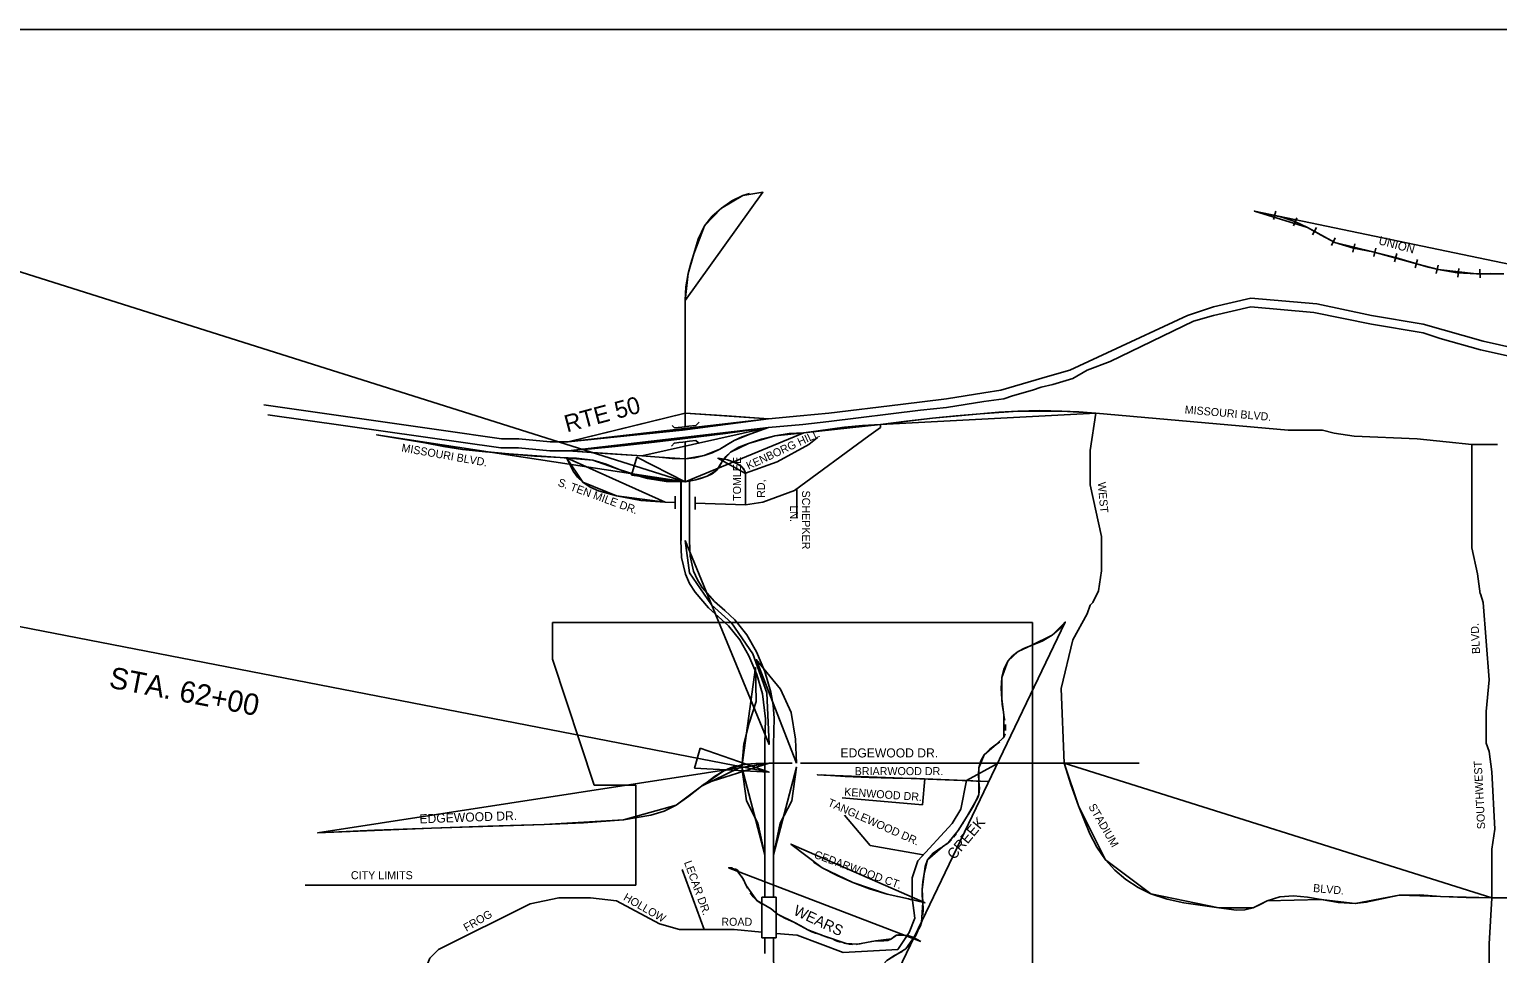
# Model space of a CAD drawing. Extents: x 5.01 to 9.58, y 0.27 to 3.39.
# Drawn here: x 6.043 to 8.037, y 1.964 to 3.219 of the extents above; entities that cross this region are included whole.
import ezdxf

# ---------------------------------------------------------------- set-up
doc = ezdxf.new("R2010")
doc.units = 0
for name, color, linetype in [('Level 7', 7, 'Continuous'), ('MO_001_NOSHOW', 7, 'Continuous'), ('MO_001_VIEW_99', 7, 'Continuous'), ('MO_001_VIEW_PV', 7, 'Continuous')]:
    doc.layers.add(name, color=color, linetype=linetype)

msp = doc.modelspace()

# ---------------------------------------------------------------- linework, layer by layer
at = {"layer": 'Level 7'}
for p, q in [((5.3044, 3.119), (6.9335, 2.6046)), ((6.8604, 2.6137), (6.8679, 2.6381)), ((6.9333, 2.6046), (6.8679, 2.6381)), ((6.8604, 2.6137), (6.9333, 2.6046)), ((5.9971, 2.4143), (7.0472, 2.2101))]:
    msp.add_line(p, q, dxfattribs=at)
msp.add_lwpolyline([(6.9535, 2.2429), (6.9462, 2.2156), (7.0472, 2.2101)], close=True, dxfattribs=at)
at = {"layer": 'MO_001_NOSHOW'}
for points in [[(6.9334, 2.8512), (6.9373, 2.8879), (6.945, 2.9143), (6.9595, 2.9527), (6.9826, 2.9766), (7.0116, 2.9937), (7.0389, 2.998)], [(6.7745, 2.6592), (6.9334, 2.6981)], [(6.9334, 2.6981), (7.0465, 2.6904)], [(7.1984, 2.6828), (7.2692, 2.691), (7.3338, 2.6971), (7.3851, 2.7008), (7.4448, 2.7008), (7.4909, 2.6981)], [(6.7745, 2.6592), (6.9295, 2.6748), (7.0465, 2.6904)], [(6.7745, 2.6592), (6.9334, 2.6759), (7.0465, 2.6904)], [(6.7745, 2.6468), (6.8381, 2.6528), (6.9295, 2.6631), (7.0465, 2.6787)], [(6.8745, 2.6399), (6.8982, 2.6383), (6.9334, 2.6358), (6.9589, 2.6406), (6.9802, 2.6492), (6.9997, 2.661), (7.0223, 2.67), (7.0465, 2.6787)], [(7.0944, 2.6714), (7.1497, 2.6788), (7.1984, 2.6828)], [(6.9334, 2.6046), (6.8823, 2.6092), (6.8439, 2.6216), (6.808, 2.634), (6.7634, 2.6377), (6.694, 2.6426), (6.6308, 2.6488), (6.58, 2.6575), (6.5143, 2.6687)], [(6.9334, 2.6046), (6.948, 2.6075), (6.963, 2.6122), (6.9761, 2.6206), (6.9835, 2.6323), (6.9948, 2.6449), (7.0191, 2.657), (7.0551, 2.6673), (7.0944, 2.6714)], [(6.772, 2.6374), (6.7943, 2.6042), (6.8402, 2.5856), (6.9062, 2.5773)], [(6.7745, 2.6468), (6.8745, 2.6399)], [(7.0154, 2.6159), (7.0141, 2.6203), (7.0096, 2.6257), (7.0032, 2.6294), (6.9991, 2.6315), (6.9949, 2.6332), (6.991, 2.6344), (6.9869, 2.6356), (6.9778, 2.6367)], [(6.9334, 2.5249), (6.9392, 2.4813), (6.9692, 2.4377), (6.9964, 2.4133), (7.025, 2.3711), (7.044, 2.318), (7.0473, 2.2481)], [(7.0844, 2.2226), (7.0833, 2.255), (7.0772, 2.2915), (7.0626, 2.3231), (7.0298, 2.3632)], [(7.0103, 2.217), (7.0128, 2.249), (7.0201, 2.2769), (7.0298, 2.3061), (7.0286, 2.3523)], [(7.0473, 2.2226), (7.0058, 2.2158), (6.9553, 2.1913), (6.9211, 2.1653), (6.8494, 2.1457), (6.7419, 2.1392), (6.5888, 2.1343), (6.4341, 2.1278)], [(6.9613, 2.1955), (6.9859, 2.212), (7.01, 2.2204), (7.0292, 2.2219), (7.0473, 2.2226)], [(7.0415, 2.0982), (7.0322, 2.1408), (7.0164, 2.1712), (7.0103, 2.217)], [(7.0532, 2.0982), (7.0624, 2.1408), (7.0782, 2.1712), (7.0844, 2.217)], [(7.448, 2.2226), (7.4673, 2.1647), (7.5039, 2.0914), (7.5656, 2.0452), (7.6582, 2.0259), (7.7045, 2.0259), (7.7237, 2.0355), (7.797, 2.0374), (7.8433, 2.0317), (7.9031, 2.0432), (7.959, 2.0413), (8.0288, 2.0394)], [(7.3444, 2.1976), (7.3138, 2.1989), (7.2473, 2.2016), (7.1834, 2.2029), (7.1129, 2.2069)], [(7.2592, 2.0326), (7.2366, 2.038), (7.2074, 2.0446), (7.1608, 2.0606), (7.1195, 2.0805), (7.077, 2.1125)], [(7.2533, 1.9801), (7.2426, 1.9863), (7.2311, 1.989), (7.2204, 1.989), (7.2133, 1.9837), (7.192, 1.981), (7.1672, 1.9766), (7.1521, 1.9774), (7.121, 1.9881), (7.0997, 1.9961), (7.0811, 2.0067), (7.0589, 2.0174), (7.05, 2.0245), (7.0305, 2.036), (7.0163, 2.0564), (7.0119, 2.0653), (7.0021, 2.0786), (6.9923, 2.0804)]]:
    msp.add_lwpolyline(points, close=True, dxfattribs=at)
for points in [[(8.0448, 2.8875), (8.0078, 2.8875), (7.956, 2.893), (7.9283, 2.9004), (7.8673, 2.9171), (7.8155, 2.93), (7.7785, 2.9503), (7.7064, 2.9725), (8.9144, 2.7205)], [(7.1814, 1.855), (7.4494, 2.4141), (7.4317, 2.3964), (7.4033, 2.3822), (7.3855, 2.3742), (7.3713, 2.3609), (7.3633, 2.3387), (7.3633, 2.3094), (7.366, 2.2881), (7.366, 2.2579), (7.3562, 2.2482), (7.3394, 2.234), (7.3323, 2.2162), (7.3323, 2.1976), (7.3323, 2.1798), (7.3287, 2.1718), (7.3163, 2.1505), (7.3039, 2.131), (7.2906, 2.1141), (7.2826, 2.1088), (7.2622, 2.0911), (7.2577, 2.0724), (7.2551, 2.0511), (7.2559, 2.0334), (7.2542, 2.0059), (7.248, 1.9917), (7.2329, 1.9703), (7.2071, 1.9544)]]:
    msp.add_lwpolyline(points, dxfattribs=at)
at = {"layer": 'MO_001_VIEW_99'}
msp.add_line((5.014, 3.2194), (9.5796, 3.2194), dxfattribs=at)
at = {"layer": 'MO_001_VIEW_PV'}
for p, q in [((7.7324, 2.9611), (7.7353, 2.9724)), ((7.7596, 2.9526), (7.7638, 2.9634)), ((7.785, 2.9401), (7.7908, 2.9501)), ((7.8109, 2.9256), (7.8159, 2.9362)), ((7.8399, 2.9165), (7.8425, 2.9279)), ((7.8686, 2.9108), (7.8712, 2.9221)), ((7.8966, 2.9036), (7.8998, 2.9149)), ((7.9246, 2.8955), (7.9279, 2.9066)), ((7.9531, 2.8876), (7.9557, 2.8991)), ((7.9827, 2.8829), (7.9838, 2.8944)), ((8.0127, 2.8817), (8.0124, 2.8934)), ((6.9335, 2.8513), (6.9335, 2.6796)), ((7.7521, 2.6747), (7.4909, 2.6982)), ((6.9156, 2.6811), (6.919, 2.6779)), ((6.948, 2.6814), (6.9522, 2.6856)), ((7.7872, 2.6747), (7.7521, 2.6747)), ((7.7988, 2.6747), (7.7872, 2.6747)), ((7.8144, 2.6708), (7.7988, 2.6747)), ((6.9148, 2.6533), (6.919, 2.6575)), ((6.9335, 2.6592), (6.9335, 2.6357)), ((6.948, 2.6609), (6.9512, 2.6578)), ((7.8417, 2.6669), (7.8144, 2.6708)), ((7.9275, 2.6631), (7.8417, 2.6669)), ((7.9665, 2.6592), (7.9275, 2.6631)), ((8.0015, 2.6553), (7.9665, 2.6592)), ((8.0366, 2.6553), (8.0015, 2.6553)), ((6.9275, 2.6046), (6.9275, 2.5248)), ((6.9277, 2.6044), (6.9277, 2.5248)), ((6.9393, 2.6046), (6.9393, 2.5248)), ((7.0851, 2.5954), (7.0851, 2.5563)), ((6.9199, 2.5767), (6.9062, 2.5773)), ((6.9199, 2.5854), (6.9199, 2.5682)), ((6.9471, 2.5844), (6.9471, 2.5673)), ((7.0152, 2.5734), (6.9471, 2.5759)), ((8.0094, 2.4799), (8.0015, 2.515)), ((8.0131, 2.4525), (8.0094, 2.4799)), ((8.017, 2.4409), (8.0133, 2.4525)), ((8.0249, 2.3357), (8.017, 2.4409)), ((6.7533, 2.4135), (7.4051, 2.4135)), ((6.7533, 2.4135), (6.7533, 2.364)), ((7.4051, 2.4135), (7.4051, 1.6251)), ((6.7533, 2.364), (6.8098, 2.1927)), ((8.021, 2.2928), (8.0249, 2.3356)), ((7.0415, 2.2482), (7.0415, 2.0403)), ((7.0532, 2.2482), (7.0532, 2.0403)), ((7.0474, 2.2227), (7.0786, 2.2227)), ((7.0901, 2.2227), (7.5498, 2.2227)), ((7.2554, 2.166), (7.2586, 2.2012)), ((6.8098, 2.1927), (6.8664, 2.1927)), ((6.8664, 2.1927), (6.8664, 2.0567)), ((7.1467, 2.1754), (7.2554, 2.166)), ((7.1844, 2.1105), (7.1496, 2.1519)), ((8.0288, 2.1057), (8.0327, 2.1329)), ((7.1844, 2.1105), (7.2564, 2.0979)), ((8.0288, 2.0393), (8.0288, 2.1057)), ((6.959, 1.9965), (6.9294, 2.0779)), ((6.4175, 2.0567), (6.8664, 2.0567)), ((7.0375, 2.0403), (7.0571, 2.0403)), ((7.0375, 2.0403), (7.0375, 1.9854)), ((7.0571, 2.0403), (7.0571, 1.9854)), ((8.0249, 1.977), (8.0288, 2.0393)), ((7.0375, 1.9854), (7.0571, 1.9854)), ((7.0415, 1.9854), (7.0415, 1.9638)), ((7.0532, 1.9854), (7.0532, 1.9638)), ((8.0249, 1.9341), (8.0249, 1.977))]:
    msp.add_line(p, q, dxfattribs=at)
for points in [[(6.9334, 2.8512), (6.9344, 2.8697), (6.9373, 2.8879), (6.941, 2.9011), (6.945, 2.9143), (6.9511, 2.9342), (6.9595, 2.9527), (6.9699, 2.9655), (6.9826, 2.9766), (6.9965, 2.9864), (7.0116, 2.9937), (7.0161, 2.9951), (7.0208, 2.9962)], [(8.0448, 2.8875), (8.0264, 2.8879), (8.0078, 2.8875), (7.9817, 2.8888), (7.956, 2.893), (7.9421, 2.8965), (7.9283, 2.9004), (7.898, 2.9093), (7.8673, 2.9171), (7.8409, 2.9223), (7.8155, 2.93), (7.7969, 2.9398), (7.7785, 2.9503), (7.7613, 2.9582), (7.7434, 2.9642), (7.7064, 2.9725)], [(7.0465, 2.6904), (7.0894, 2.6942), (7.1283, 2.6981), (7.2258, 2.7098), (7.2882, 2.7176), (7.3388, 2.7254), (7.3622, 2.7293), (7.4285, 2.7488), (7.4558, 2.7566), (7.5065, 2.78), (7.6156, 2.8307), (7.6507, 2.8424), (7.7014, 2.8541), (7.791, 2.8463), (7.8651, 2.8307), (7.9353, 2.819), (7.9625, 2.8112), (8.0171, 2.7956), (8.3134, 2.7293), (8.403, 2.7176), (8.4147, 2.7176), (8.4303, 2.7176)], [(7.0465, 2.6787), (7.0933, 2.6826), (7.1283, 2.6865), (7.2531, 2.702), (7.2882, 2.7059), (7.3388, 2.7137), (7.3661, 2.7176), (7.3778, 2.7215), (7.4051, 2.7293), (7.4168, 2.7332), (7.4324, 2.7371), (7.4597, 2.7449), (7.4792, 2.7566), (7.5104, 2.7683), (7.6234, 2.8229), (7.6507, 2.8307), (7.7014, 2.8424), (7.7871, 2.8346), (7.8651, 2.819), (7.9353, 2.8073), (7.9586, 2.7995), (8.0132, 2.7839), (8.3134, 2.7176), (8.3711, 2.7076)], [(6.3612, 2.7092), (6.6021, 2.6748), (6.684, 2.6631), (6.7073, 2.6631), (6.7502, 2.6592), (6.7745, 2.6592)], [(6.3667, 2.6959), (6.6831, 2.6507), (6.7068, 2.6507), (6.7497, 2.6468), (6.7745, 2.6468)], [(6.7745, 2.6592), (6.854, 2.6786), (6.9334, 2.6981)], [(6.9334, 2.6981), (6.99, 2.6942), (7.0465, 2.6904)], [(7.1984, 2.6828), (7.2338, 2.6871), (7.2692, 2.691), (7.3015, 2.6942), (7.3338, 2.6971), (7.3594, 2.6993), (7.3851, 2.7008), (7.4149, 2.7014), (7.4448, 2.7008), (7.4679, 2.6997), (7.4909, 2.6981)], [(7.4831, 2.437), (7.487, 2.4409), (7.4948, 2.4565), (7.4987, 2.4838), (7.4987, 2.5305), (7.4831, 2.6007), (7.4831, 2.6475), (7.4909, 2.6981)], [(6.7745, 2.6592), (6.8541, 2.667), (6.9334, 2.6759), (6.99, 2.6829), (7.0465, 2.6904)], [(6.7745, 2.6468), (6.8063, 2.6497), (6.8381, 2.6528), (6.8839, 2.6577), (6.9295, 2.6631), (6.9881, 2.6705), (7.0465, 2.6787)], [(6.8745, 2.6399), (6.8863, 2.6392), (6.8982, 2.6383), (6.9158, 2.6364), (6.9334, 2.6358), (6.9463, 2.6374), (6.9589, 2.6406), (6.9698, 2.6443), (6.9802, 2.6492), (6.9899, 2.6551), (6.9997, 2.661), (7.0108, 2.6659), (7.0223, 2.67), (7.0344, 2.6744), (7.0465, 2.6787)], [(6.9189, 2.6779), (6.924, 2.6785), (6.929, 2.6791), (6.9385, 2.6802), (6.9479, 2.6814)], [(7.0816, 2.5929), (7.1829, 2.667), (7.1985, 2.6787), (7.1985, 2.6826), (7.1984, 2.6828)], [(7.1461, 2.6784), (7.1479, 2.6786), (7.1497, 2.6788), (7.174, 2.6811), (7.1984, 2.6828)], [(6.9334, 2.6046), (6.9077, 2.6053), (6.8823, 2.6092), (6.8629, 2.6147), (6.8439, 2.6216), (6.8261, 2.6285), (6.808, 2.634), (6.7859, 2.6368), (6.7634, 2.6377), (6.7286, 2.6398), (6.694, 2.6426), (6.6623, 2.6453), (6.6308, 2.6488), (6.6053, 2.6529), (6.58, 2.6575), (6.5472, 2.6632), (6.5143, 2.6687)], [(6.9189, 2.6574), (6.9245, 2.6581), (6.9301, 2.6588), (6.939, 2.6598), (6.9479, 2.6609)], [(6.9334, 2.6046), (6.9408, 2.6059), (6.948, 2.6075), (6.9555, 2.6095), (6.963, 2.6122), (6.9701, 2.6157), (6.9761, 2.6206), (6.98, 2.6262), (6.9835, 2.6323), (6.9886, 2.6391), (6.9948, 2.6449), (7.0063, 2.6519), (7.0191, 2.657), (7.037, 2.6629), (7.0551, 2.6673), (7.0747, 2.6702), (7.0944, 2.6714)], [(7.0153, 2.5734), (7.0153, 2.6163), (7.0582, 2.6319), (7.1011, 2.6553), (7.1132, 2.6649)], [(8.0015, 2.5149), (8.0015, 2.5188), (8.0015, 2.589), (8.0015, 2.6553)], [(6.772, 2.6374), (6.7812, 2.6193), (6.7872, 2.6112), (6.7943, 2.6042), (6.8045, 2.5975), (6.8158, 2.5924), (6.8402, 2.5856), (6.8732, 2.5794), (6.9062, 2.5773)], [(6.7745, 2.6468), (6.8245, 2.6434), (6.8745, 2.6399)], [(6.9334, 2.6358), (6.9334, 2.6358), (6.9334, 2.6241), (6.9334, 2.6124), (6.9334, 2.6046)], [(7.0153, 2.6167), (7.0148, 2.6185), (7.0141, 2.6203), (7.0122, 2.6232), (7.0096, 2.6257), (7.0065, 2.6277), (7.0032, 2.6294), (7.0012, 2.6304), (6.9991, 2.6315), (6.997, 2.6324), (6.9949, 2.6332), (6.993, 2.6338), (6.991, 2.6344), (6.989, 2.635), (6.9869, 2.6356), (6.9865, 2.6358), (6.986, 2.6359)], [(7.0153, 2.5734), (7.0387, 2.5773), (7.0816, 2.5929)], [(6.9276, 2.5252), (6.9283, 2.5019), (6.9337, 2.4793), (6.9394, 2.4666), (6.9467, 2.4547), (6.9651, 2.4335), (6.9788, 2.4214), (6.9922, 2.4092), (7.0075, 2.39), (7.0197, 2.3684), (7.0307, 2.3431), (7.0383, 2.3167), (7.0426, 2.2829), (7.0415, 2.2488)], [(6.9393, 2.5245), (6.9399, 2.5036), (6.9447, 2.4833), (6.9499, 2.4718), (6.9565, 2.4611), (6.9732, 2.442), (6.9871, 2.4297), (7.0006, 2.4173), (7.017, 2.3968), (7.0302, 2.3737), (7.0417, 2.347), (7.0497, 2.3192), (7.0528, 2.3015), (7.0543, 2.2835), (7.0532, 2.2475)], [(7.448, 2.2226), (7.4441, 2.3239), (7.4597, 2.3902), (7.4792, 2.4253), (7.4831, 2.437)], [(7.4494, 2.4141), (7.4412, 2.4046), (7.4317, 2.3964), (7.418, 2.3884), (7.4033, 2.3822), (7.3942, 2.3786), (7.3855, 2.3742), (7.3777, 2.3683), (7.3713, 2.3609), (7.3661, 2.3503), (7.3633, 2.3387), (7.3625, 2.324), (7.3633, 2.3094), (7.364, 2.3021), (7.365, 2.2947)], [(7.366, 2.2879), (7.3667, 2.2845), (7.3673, 2.2811)], [(7.3682, 2.275), (7.3685, 2.2709), (7.3685, 2.2669)], [(8.0249, 2.2382), (8.021, 2.2499), (8.021, 2.2927)], [(7.3678, 2.2623), (7.367, 2.26), (7.366, 2.2579), (7.3656, 2.2572), (7.3651, 2.2564)], [(7.3605, 2.2516), (7.3584, 2.2498), (7.3562, 2.2482), (7.3472, 2.2415), (7.3394, 2.234), (7.3348, 2.2256), (7.3323, 2.2162), (7.3317, 2.2069), (7.3323, 2.1976), (7.3331, 2.1885), (7.3323, 2.1798), (7.3307, 2.1758), (7.3287, 2.1718), (7.3235, 2.1624), (7.318, 2.1532)], [(8.0327, 2.1329), (8.0288, 2.2109), (8.0249, 2.2382)], [(6.9613, 2.1955), (6.973, 2.2046), (6.9859, 2.212), (6.995, 2.2161), (7.0045, 2.2192)], [(7.0162, 2.2212), (7.0227, 2.2216), (7.0292, 2.2219), (7.0383, 2.2223), (7.0473, 2.2226)], [(7.3155, 2.1992), (7.3583, 2.2226), (7.3621, 2.2226)], [(7.448, 2.2226), (7.4569, 2.1935), (7.4673, 2.1647), (7.4828, 2.1265), (7.4924, 2.1083), (7.5039, 2.0914), (7.517, 2.077), (7.5319, 2.0644), (7.5483, 2.0537), (7.5656, 2.0452), (7.5877, 2.0377), (7.6106, 2.0328), (7.6582, 2.0259), (7.682, 2.023), (7.6935, 2.0233), (7.7045, 2.0259), (7.7141, 2.0305), (7.7237, 2.0355), (7.741, 2.0408), (7.7594, 2.0421), (7.7782, 2.0406), (7.797, 2.0374), (7.8204, 2.0331), (7.8433, 2.0317), (7.8582, 2.0335), (7.8731, 2.0369), (7.9031, 2.0432), (7.9309, 2.0436), (7.959, 2.0413), (7.9939, 2.0399), (8.0288, 2.0394)], [(6.9613, 2.1955), (6.9583, 2.1934), (6.9553, 2.1913), (6.9383, 2.1779), (6.9211, 2.1653), (6.9046, 2.1572), (6.8869, 2.1518), (6.8494, 2.1457), (6.7954, 2.1414), (6.7419, 2.1392), (6.6655, 2.1368), (6.5888, 2.1343), (6.5114, 2.1313), (6.4341, 2.1278)], [(7.3444, 2.1976), (7.3291, 2.1983), (7.3138, 2.1989), (7.2805, 2.2004), (7.2473, 2.2016), (7.2153, 2.2022), (7.1834, 2.2029), (7.1507, 2.2044), (7.1181, 2.2065)], [(7.2492, 2.09), (7.296, 2.1407), (7.3077, 2.1602), (7.3155, 2.1992)], [(7.3072, 2.1362), (7.3061, 2.1345), (7.305, 2.1327)], [(7.3136, 2.1462), (7.3117, 2.1431), (7.3097, 2.1401)], [(7.2948, 2.1182), (7.2927, 2.1161), (7.2906, 2.1141), (7.2895, 2.1133), (7.2884, 2.1125)], [(7.3011, 2.1266), (7.2994, 2.1242), (7.2977, 2.1218)], [(7.2805, 2.1075), (7.27, 2.1003), (7.2622, 2.0911), (7.2592, 2.0821), (7.2577, 2.0724), (7.2561, 2.0617), (7.2551, 2.0511), (7.2553, 2.0423), (7.2559, 2.0334), (7.2564, 2.0247), (7.256, 2.016)], [(6.9974, 2.0802), (6.9949, 2.0804), (6.9923, 2.0804)], [(7.007, 2.0741), (7.005, 2.0765), (7.0025, 2.0784)], [(7.2418, 2.0368), (7.2392, 2.0374), (7.2366, 2.038), (7.2219, 2.0412), (7.2074, 2.0446), (7.1838, 2.0518), (7.1608, 2.0606), (7.1398, 2.0698), (7.1195, 2.0805), (7.1134, 2.0843), (7.1074, 2.0882)], [(7.2219, 1.9692), (7.2375, 1.9926), (7.2453, 2.0121), (7.2414, 2.0394), (7.2414, 2.0667), (7.2492, 2.09)], [(7.0126, 2.0638), (7.0122, 2.0646), (7.0119, 2.0653), (7.0109, 2.0673), (7.01, 2.0692)], [(7.0181, 2.0529), (7.0172, 2.0547), (7.0163, 2.0564), (7.0158, 2.0575), (7.0152, 2.0585)], [(6.4306, 1.747), (6.4384, 1.7938), (6.4423, 1.8094), (6.4696, 1.8562), (6.4813, 1.8718), (6.5514, 1.899), (6.5709, 1.9185), (6.5865, 1.9575), (6.5982, 1.9692), (6.723, 2.0316), (6.7619, 2.0394), (6.8048, 2.0394), (6.8399, 2.0355), (6.8984, 2.0043), (6.9257, 1.9965), (6.9997, 1.9965), (7.0376, 1.993)], [(7.0376, 2.0315), (7.0339, 2.0336), (7.0305, 2.036), (7.0257, 2.0409), (7.0217, 2.0465)], [(8.2276, 2.0433), (8.0912, 2.0394), (8.0288, 2.0394)], [(7.1115, 1.9913), (7.1055, 1.9935), (7.0997, 1.9961), (7.0904, 2.0014), (7.0811, 2.0067), (7.0697, 2.0117), (7.0589, 2.0174), (7.058, 2.0181), (7.0571, 2.0188)], [(7.2542, 2.0061), (7.2542, 2.006), (7.2542, 2.0059), (7.2527, 2.0017), (7.251, 1.9977)], [(7.0571, 1.9913), (7.0855, 1.9887), (7.1478, 1.9653), (7.2219, 1.9692)], [(7.1283, 1.9853), (7.1247, 1.9867), (7.121, 1.9881), (7.1195, 1.9886), (7.118, 1.9892)], [(7.1442, 1.9794), (7.1397, 1.9809), (7.1352, 1.9826)], [(7.1604, 1.9764), (7.1562, 1.9768), (7.1521, 1.9774), (7.1505, 1.9778), (7.149, 1.9781)], [(7.1746, 1.9778), (7.1709, 1.9771), (7.1672, 1.9766), (7.1664, 1.9765), (7.1655, 1.9764)], [(7.2446, 1.9855), (7.2436, 1.9859), (7.2426, 1.9863), (7.237, 1.9879), (7.2311, 1.989), (7.2256, 1.9897), (7.2204, 1.989), (7.2168, 1.9865), (7.2133, 1.9837), (7.2086, 1.9816), (7.2033, 1.981), (7.192, 1.981), (7.1867, 1.9804), (7.1816, 1.9794)], [(7.2409, 1.9795), (7.2379, 1.9754), (7.2345, 1.9718)], [(7.2477, 1.9912), (7.2456, 1.9872), (7.2434, 1.9833)], [(7.1728, 1.2871), (7.1508, 1.3444), (7.1294, 1.4008), (7.1012, 1.4767), (7.0883, 1.5151), (7.077, 1.5539), (7.0692, 1.5866), (7.0629, 1.6196), (7.0581, 1.6529), (7.055, 1.6863), (7.0532, 1.7317), (7.0534, 1.7771), (7.055, 1.8679), (7.0544, 1.9159), (7.0532, 1.9639)], [(7.2278, 1.9669), (7.2174, 1.9613), (7.2071, 1.9544), (7.2027, 1.9494), (7.2009, 1.9437), (7.2043, 1.935), (7.2071, 1.9269), (7.2032, 1.921), (7.1965, 1.9153), (7.1906, 1.9077), (7.1867, 1.8993), (7.182, 1.8859), (7.1796, 1.8718), (7.1799, 1.8633), (7.1814, 1.855)]]:
    msp.add_lwpolyline(points, dxfattribs=at)

# ---------------------------------------------------------------- texts
at = {"layer": 'Level 7'}
msp.add_text('STA. 62+00', height=0.02899, rotation=349.0998, dxfattribs=at).set_placement((6.1496, 2.3254))
at = {"layer": 'MO_001_VIEW_PV'}
for s, height, rotation, p in [('UNION', 0.01159, 345, (7.8741, 2.9276)), ('RTE 50', 0.02319, 15, (6.7728, 2.6718)), ('MISSOURI BLVD.', 0.01087, 355, (7.6113, 2.6977)), ('KENBORG HILL', 0.01087, 25, (7.0194, 2.6209)), ('MISSOURI BLVD.', 0.01087, 350, (6.5475, 2.646)), ('TOMLEE', 0.01087, 90, (7.0091, 2.5789)), ('S. TEN MILE DR.', 0.01087, 340, (6.7595, 2.5996)), (' RD,', 0.01087, 90, (7.0417, 2.5789)), ('SCHEPKER', 0.01087, 270, (7.0921, 2.5929)), ('WEST', 0.01087, 275, (7.4936, 2.604)), ('     LN.', 0.01087, 270, (7.0758, 2.5929)), ('BLVD.', 0.01087, 93, (8.0128, 2.3712)), ('SOUTHWEST', 0.01087, 93, (8.0198, 2.1331)), ('TANGLEWOOD DR.', 0.01087, 336, (7.1259, 2.165)), ('KENWOOD DR.', 0.01087, 356, (7.149, 2.1784)), ('EDGEWOOD DR.', 0.01232, 2, (6.5727, 2.1407)), ('STADIUM', 0.01087, 300, (7.4805, 2.1636)), ('CREEK', 0.01449, 50, (7.2987, 2.0905)), ('CEDARWOOD CT.', 0.01087, 340, (7.1075, 2.0941)), ('LECAR DR.', 0.01087, 290, (6.9316, 2.0878)), ('BLVD.', 0.01087, 355, (7.7857, 2.0476)), ('HOLLOW', 0.01087, 330, (6.8484, 2.0372)), ('FROG', 0.01087, 30, (6.6362, 1.9934)), ('WEARS', 0.01449, 335, (7.0792, 2.0172))]:
    msp.add_text(s, height=height, rotation=rotation, dxfattribs=at).set_placement(p)
for s, height, p in [('EDGEWOOD DR.', 0.01232, (7.1442, 2.2303)), ('BRIARWOOD DR.', 0.01087, (7.1635, 2.2063)), ('CITY LIMITS', 0.01087, (6.4794, 2.0649)), ('ROAD', 0.01087, (6.9824, 2.0016))]:
    msp.add_text(s, height=height, dxfattribs=at).set_placement(p)

doc.saveas('drawing.dxf')
